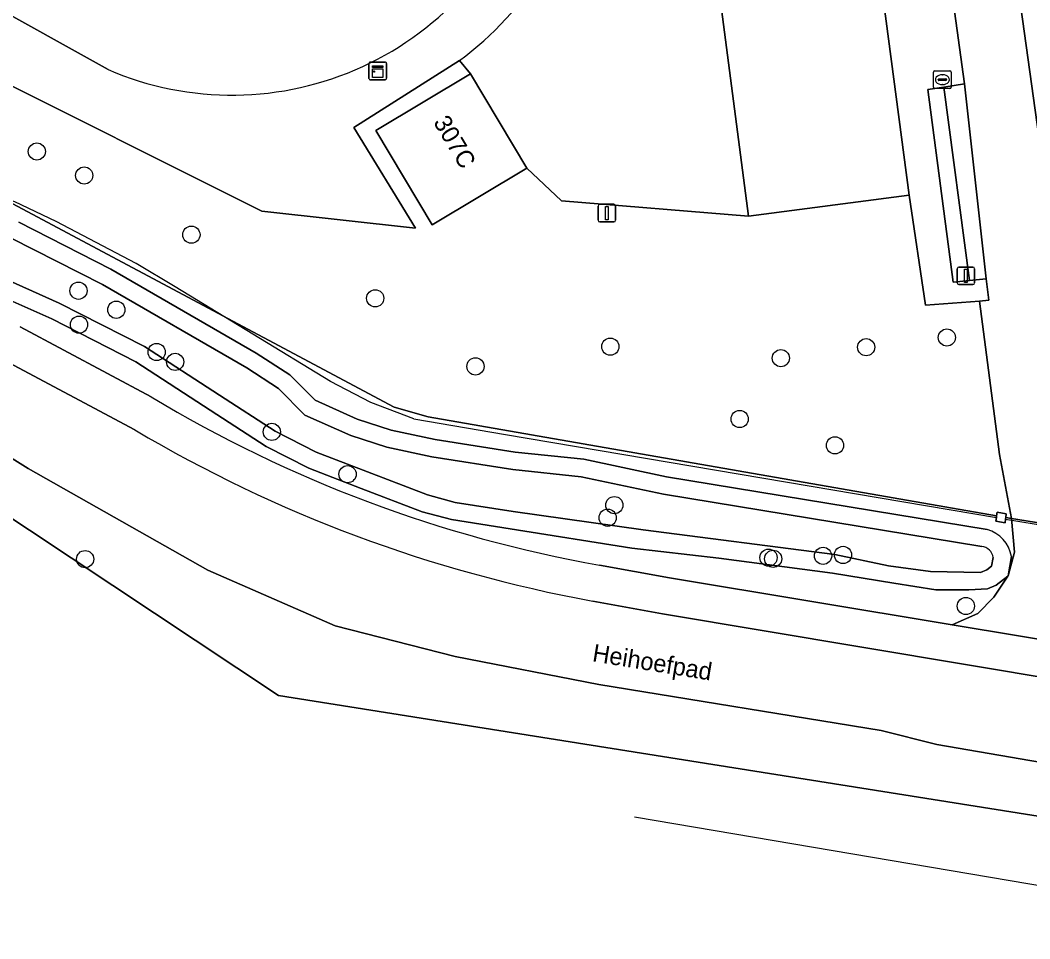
# Model space of a CAD drawing. Extents: x 162156 to 163172, y 378995 to 380779.
# Drawn here: x 162261.3 to 162318.7, y 379694.4 to 379746.6 of the extents above; entities that cross this region are included whole.
import ezdxf

# ---------------------------------------------------------------- set-up
doc = ezdxf.new("R2010")
doc.units = 0
for name, color, linetype in [('IMGEO_Boom', 7, 'Continuous'), ('IMGEO_Erf', 7, 'Continuous'), ('IMGEO_Fietspad_gesloten', 7, 'Continuous'), ('IMGEO_Grasland_overig', 7, 'Continuous'), ('IMGEO_Groenvoorziening', 7, 'Continuous'), ('IMGEO_Haag', 7, 'Continuous'), ('IMGEO_Hek', 7, 'Continuous'), ('IMGEO_Kast', 7, 'Continuous'), ('IMGEO_Kolk', 7, 'Continuous'), ('IMGEO_Lichtmast', 7, 'Continuous'), ('IMGEO_Loofbos', 7, 'Continuous'), ('IMGEO_Muur', 7, 'Continuous'), ('IMGEO_Oever', 7, 'Continuous'), ('IMGEO_Openbare_ruimte_label', 7, 'Continuous'), ('IMGEO_Pand', 7, 'Continuous'), ('IMGEO_Pand_nummerreeks', 7, 'Continuous'), ('IMGEO_Terreindeel_halfverhard', 7, 'Continuous'), ('IMGEO_Voetpad_gesloten', 7, 'Continuous'), ('IMGEO_Voetpad_open', 7, 'Continuous'), ('IMGEO_Waterloop', 7, 'Continuous')]:
    doc.layers.add(name, color=color, linetype=linetype)

msp = doc.modelspace()

# ---------------------------------------------------------------- linework, layer by layer
at = {"layer": 'IMGEO_Boom'}
for centre in [(162262.276, 379739.102), (162264.97, 379737.739), (162271.062, 379734.373), (162264.643, 379731.19), (162281.512, 379730.76), (162266.792, 379730.109), (162264.674, 379729.263), (162314.007, 379728.531), (162269.086, 379727.706), (162294.874, 379728.013), (162309.418, 379727.979), (162270.138, 379727.147), (162287.209, 379726.889), (162304.569, 379727.359), (162302.227, 379723.897), (162275.633, 379723.167), (162307.643, 379722.401), (162279.94, 379720.763), (162295.106, 379719.005), (162294.724, 379718.289), (162303.87, 379716.02), (162306.968, 379716.122), (162308.103, 379716.175), (162265.022, 379715.936), (162304.132, 379715.955), (162315.086, 379713.271)]:
    msp.add_circle(centre, 0.489, dxfattribs=at)
at = {"layer": 'IMGEO_Erf'}
msp.add_lwpolyline([(162337.174, 379688.677), (162335.238, 379695.41), (162334.723, 379697.203), (162334.223, 379698.94), (162276.018, 379708.183), (162252.426, 379723.827), (162232.664, 379729.795), (162201.08, 379730.479), (162201.347, 379726.944), (162202.006, 379718.214)], dxfattribs=at)
at = {"layer": 'IMGEO_Fietspad_gesloten'}
for points in [[(162268.773, 379725.159), (162261.33, 379729.13)], [(162260.378, 379727.269), (162267.847, 379723.281)], [(162413.482, 379695.459), (162407.265, 379696.651), (162406.548, 379696.772), (162403.9, 379697.219), (162359.692, 379704.679), (162325.622, 379710.328), (162314.3, 379712.205), (162298.239, 379714.868), (162294.268, 379715.593)], [(162293.883, 379713.556), (162297.835, 379712.825), (162406.505, 379694.666), (162426.261, 379691.023), (162431.745, 379689.857)]]:
    msp.add_lwpolyline(points, dxfattribs=at)
for centre, radius, start, end in [((162307.334, 379789.173), 74.731, 238.93594, 259.93079), ((162307.945, 379790.919), 78.631, 239.33886, 259.69768)]:
    msp.add_arc(centre, radius, start, end, dxfattribs=at)
at = {"layer": 'IMGEO_Grasland_overig'}
for points in [[(162214.541, 379733.002), (162226.745, 379733.002), (162231.259, 379732.528), (162235.614, 379731.527), (162241.895, 379730.106), (162247.114, 379728.274), (162254.858, 379725.049), (162258.235, 379723.285), (162261.79, 379721.082), (162272, 379715.314), (162279.233, 379712.147), (162286.048, 379710.401), (162294.223, 379708.812), (162310.274, 379706.198), (162313.432, 379705.394), (162326.545, 379703.142)], [(162267.847, 379723.281), (162260.378, 379727.269)], [(162297.835, 379712.825), (162293.883, 379713.556)], [(162431.745, 379689.857), (162426.261, 379691.023), (162406.505, 379694.666), (162297.835, 379712.825)]]:
    msp.add_lwpolyline(points, dxfattribs=at)
msp.add_arc((162307.945, 379790.919), 78.631, 239.33886, 259.69768, dxfattribs=at)
at = {"layer": 'IMGEO_Groenvoorziening'}
for points in [[(162308.264, 379818.798), (162308.342, 379818.234), (162319.23, 379739.952), (162323.504, 379740.549), (162323.904, 379737.397), (162326.096, 379737.669), (162325.701, 379740.847), (162354.391, 379744.94), (162352.739, 379754.146)], [(162245.107, 379755.565), (162200.542, 379780.028), (162207.281, 379761.484), (162206.713, 379759.494), (162208.417, 379755.264), (162211.499, 379752.19), (162220.789, 379751.034), (162244.456, 379751.721), (162246.14, 379754.783), (162260.156, 379747.07), (162258.472, 379744.009), (162275.07, 379735.712), (162283.803, 379734.743), (162280.296, 379740.465), (162286.296, 379744.277)], [(162266.322, 379743.758), (162245.107, 379755.565)], [(162260.586, 379736.299), (162282.584, 379724.579), (162284.522, 379724.017), (162316.836, 379718.388), (162316.869, 379718.597), (162317.383, 379718.517), (162317.353, 379718.304), (162317.673, 379718.252), (162317.006, 379721.885), (162315.86, 379730.604), (162312.79, 379730.368), (162311.854, 379736.618), (162302.724, 379735.425), (162292.108, 379736.3), (162290.138, 379738.153), (162284.754, 379734.934), (162281.544, 379740.303), (162286.928, 379743.522), (162286.296, 379744.277), (162280.296, 379740.465), (162283.803, 379734.743), (162275.07, 379735.712), (162258.472, 379744.009)], [(162296.1, 379716.558), (162289.191, 379717.652), (162285.844, 379718.182), (162284.173, 379718.63), (162280.713, 379719.958), (162277.745, 379721.098), (162275.315, 379722.336), (162272.124, 379724.409), (162267.9, 379727.151), (162263.121, 379729.586), (162259.537, 379731.182), (162256.304, 379732.621), (162252.721, 379733.786), (162245.305, 379736.068)], [(162317.68, 379716.09), (162317.487, 379714.992), (162317.854, 379716.332), (162317.673, 379718.252), (162317.353, 379718.304), (162317.34, 379718.213), (162317.31, 379718), (162316.79, 379718.091), (162316.822, 379718.298), (162316.836, 379718.388), (162284.522, 379724.017), (162282.584, 379724.579), (162260.586, 379736.299)], [(162261.252, 379735.081), (162266.481, 379732.417), (162274.735, 379727.651), (162276.648, 379726.409), (162278.096, 379724.962), (162280.479, 379723.9), (162282.421, 379723.269), (162284.911, 379722.74), (162289.465, 379722.019), (162293.375, 379721.608), (162298.069, 379720.61), (162316.295, 379717.625)], [(162261.33, 379729.13), (162268.773, 379725.159)], [(162294.268, 379715.593), (162298.239, 379714.868), (162314.3, 379712.205), (162315.759, 379712.85), (162316.676, 379713.773), (162317.48, 379714.967), (162316.802, 379714.457), (162316.306, 379714.252), (162315.256, 379714.197), (162313.385, 379714.197), (162310.997, 379714.575), (162307.496, 379715.13), (162301.046, 379715.997), (162296.1, 379716.558)]]:
    msp.add_lwpolyline(points, dxfattribs=at)
for points in [[(162314.999, 379742.94), (162313.835, 379742.763), (162315.296, 379731.777), (162316.244, 379731.87)], [(162313.835, 379742.763), (162312.925, 379742.625), (162314.36, 379731.685), (162315.296, 379731.777)]]:
    msp.add_lwpolyline(points, close=True, dxfattribs=at)
for centre, radius, start, end in [((162276.161, 379758.307), 17.307, 305.84362, 352.61508), ((162273.362, 379760.093), 17.788, 246.68434, 342.76247), ((162307.334, 379789.173), 74.731, 238.93594, 259.93079), ((162315.75, 379715.741), 1.961, 10.24618, 73.87244)]:
    msp.add_arc(centre, radius, start, end, dxfattribs=at)
at = {"layer": 'IMGEO_Haag'}
msp.add_lwpolyline([(162313.835, 379742.763), (162312.925, 379742.625), (162314.36, 379731.685), (162315.296, 379731.777)], close=True, dxfattribs=at)
at = {"layer": 'IMGEO_Hek'}
for points in [[(162266.322, 379743.758), (162245.107, 379755.565), (162200.542, 379780.028)], [(162283.7, 379723.919), (162281.26, 379724.831), (162278.962, 379726.037), (162270.138, 379731.405), (162267.925, 379732.742), (162263.368, 379735.129), (162261.032, 379736.236), (162253.819, 379738.605), (162239.147, 379743.541)], [(162283.7, 379723.919), (162288.918, 379723.028)], [(162288.918, 379723.028), (162316.822, 379718.298)], [(162317.34, 379718.213), (162322.451, 379717.379)], [(162332.134, 379695.194), (162296.257, 379701.272)]]:
    msp.add_lwpolyline(points, dxfattribs=at)
msp.add_arc((162273.362, 379760.093), 17.788, 246.68434, 342.76247, dxfattribs=at)
at = {"layer": 'IMGEO_Kast'}
for p, q in [((162281.155, 379743.255), (162281.155, 379744.096)), ((162281.155, 379744.096), (162281.155, 379743.255)), ((162281.23, 379744.18), (162282.071, 379744.18)), ((162282.071, 379744.18), (162281.23, 379744.18)), ((162282.155, 379744.105), (162282.155, 379743.264)), ((162282.155, 379743.264), (162282.155, 379744.105)), ((162282.08, 379743.18), (162281.239, 379743.18)), ((162281.239, 379743.18), (162282.08, 379743.18))]:
    msp.add_line(p, q, dxfattribs=at)
for points in [[(162281.35, 379743.97), (162281.95, 379743.97), (162281.95, 379743.885), (162281.35, 379743.885), (162281.35, 379743.97)], [(162281.35, 379743.795), (162281.95, 379743.795), (162281.95, 379743.306), (162281.35, 379743.306), (162281.35, 379743.795)]]:
    msp.add_lwpolyline(points, dxfattribs=at)
msp.add_circle((162281.434, 379743.644), 0.0377, dxfattribs=at)
for centre, start, end in [((162281.233, 379744.102), 92.4484, 184.28452), ((162281.233, 379744.102), 92.4484, 184.28452), ((162282.077, 379744.102), 2.4484, 94.28452), ((162282.077, 379744.102), 2.4484, 94.28452), ((162281.233, 379743.258), 182.4484, 274.28452), ((162281.233, 379743.258), 182.4484, 274.28452), ((162282.077, 379743.258), 272.4484, 4.28452), ((162282.077, 379743.258), 272.4484, 4.28452)]:
    msp.add_arc(centre, 0.0779, start, end, dxfattribs=at)
at = {"layer": 'IMGEO_Kolk'}
for p, q in [((162313.25, 379742.758), (162313.25, 379743.61)), ((162313.325, 379743.684), (162314.177, 379743.684)), ((162313.738, 379743.464), (162313.763, 379743.464)), ((162314.251, 379743.61), (162314.251, 379742.758)), ((162313.509, 379743.178), (162313.509, 379743.19)), ((162313.947, 379743.141), (162313.549, 379743.141)), ((162313.552, 379743.227), (162313.95, 379743.227)), ((162313.761, 379742.904), (162313.736, 379742.904)), ((162313.993, 379743.19), (162313.993, 379743.178)), ((162314.177, 379742.684), (162313.325, 379742.684))]:
    msp.add_line(p, q, dxfattribs=at)
for points in [[(162313.25, 379742.758), (162313.25, 379743.61)], [(162313.325, 379743.684), (162314.177, 379743.684)], [(162314.251, 379743.61), (162314.251, 379742.758)], [(162314.177, 379742.684), (162313.325, 379742.684)]]:
    msp.add_lwpolyline(points, dxfattribs=at)
for centre, radius, start, end in [((162313.327, 379743.608), 0.0765, 91.55205, 178.44795), ((162313.327, 379743.608), 0.0765, 91.55205, 178.44795), ((162314.175, 379743.608), 0.0765, 1.55205, 88.44795), ((162314.175, 379743.608), 0.0765, 1.55205, 88.44795), ((162313.549, 379743.187), 0.0403, 85.87752, 175.75265), ((162313.546, 379743.177), 0.0366, 178.93798, 274.71019), ((162313.95, 379743.184), 0.043, 264.86636, 352.45326), ((162313.954, 379743.189), 0.0386, 1.73085, 96.63898), ((162313.327, 379742.76), 0.0765, 181.55205, 268.44795), ((162313.327, 379742.76), 0.0765, 181.55205, 268.44795), ((162314.175, 379742.76), 0.0765, 271.55205, 358.44795), ((162314.175, 379742.76), 0.0765, 271.55205, 358.44795)]:
    msp.add_arc(centre, radius, start, end, dxfattribs=at)
for centre, major_axis, ratio, start_param, end_param in [((162313.737, 379743.184), (-0.387, 0.002), 0.722429, 4.712389, 7.853982), ((162313.762, 379743.184), (-0.39, 0.002), 0.717154, 1.570796, 4.712389)]:
    msp.add_ellipse(centre, major_axis=major_axis, ratio=ratio, start_param=start_param, end_param=end_param, dxfattribs=at)
at = {"layer": 'IMGEO_Lichtmast'}
for p, q in [((162294.181, 379735.202), (162294.181, 379736.002)), ((162294.181, 379736.002), (162294.181, 379735.202)), ((162294.281, 379736.102), (162295.071, 379736.102)), ((162295.071, 379736.102), (162294.281, 379736.102)), ((162295.171, 379736.002), (162295.171, 379735.202)), ((162295.171, 379735.202), (162295.171, 379736.002)), ((162295.071, 379735.102), (162294.281, 379735.102)), ((162294.281, 379735.102), (162295.071, 379735.102)), ((162314.691, 379732.538), (162315.481, 379732.538)), ((162315.481, 379732.538), (162314.691, 379732.538)), ((162314.591, 379731.638), (162314.591, 379732.438)), ((162314.591, 379732.438), (162314.591, 379731.638)), ((162315.581, 379732.438), (162315.581, 379731.638)), ((162315.581, 379731.638), (162315.581, 379732.438)), ((162315.481, 379731.538), (162314.691, 379731.538)), ((162314.691, 379731.538), (162315.481, 379731.538))]:
    msp.add_line(p, q, dxfattribs=at)
for points in [[(162294.601, 379735.977), (162294.751, 379735.977), (162294.751, 379735.227), (162294.601, 379735.227), (162294.601, 379735.977)], [(162315.011, 379732.413), (162315.161, 379732.413), (162315.161, 379731.663), (162315.011, 379731.663), (162315.011, 379732.413)]]:
    msp.add_lwpolyline(points, dxfattribs=at)
for centre, start, end in [((162294.281, 379736.002), 90, 180), ((162294.281, 379736.002), 90, 180), ((162295.071, 379736.002), 0, 90), ((162295.071, 379736.002), 360, 90), ((162294.281, 379735.202), 180, 270), ((162294.281, 379735.202), 180, 270), ((162295.071, 379735.202), 270, 0), ((162295.071, 379735.202), 270, 0), ((162314.691, 379732.438), 90, 180), ((162314.691, 379732.438), 90, 180), ((162315.481, 379732.438), 0, 90), ((162315.481, 379732.438), 360, 90), ((162314.691, 379731.638), 180, 270), ((162314.691, 379731.638), 180, 270), ((162315.481, 379731.638), 270, 0), ((162315.481, 379731.638), 270, 0)]:
    msp.add_arc(centre, 0.1, start, end, dxfattribs=at)
at = {"layer": 'IMGEO_Loofbos'}
for points in [[(162235.614, 379731.527), (162231.259, 379732.528), (162226.745, 379733.002), (162214.541, 379733.002), (162205.491, 379732.528), (162200.706, 379732.277), (162201.08, 379730.479), (162232.664, 379729.795), (162252.426, 379723.827), (162276.018, 379708.183), (162334.223, 379698.94), (162336.989, 379698.762)], [(162329.924, 379702.799), (162326.545, 379703.142), (162313.432, 379705.394), (162310.274, 379706.198), (162294.223, 379708.812), (162286.048, 379710.401), (162279.233, 379712.147), (162272, 379715.314), (162261.79, 379721.082), (162258.235, 379723.285), (162254.858, 379725.049), (162247.114, 379728.274), (162241.895, 379730.106), (162235.614, 379731.527)]]:
    msp.add_lwpolyline(points, dxfattribs=at)
at = {"layer": 'IMGEO_Muur'}
msp.add_lwpolyline([(162317.353, 379718.304), (162317.383, 379718.517), (162316.869, 379718.597), (162316.836, 379718.388), (162316.822, 379718.298), (162316.79, 379718.091), (162317.31, 379718), (162317.34, 379718.213)], close=True, dxfattribs=at)
at = {"layer": 'IMGEO_Oever'}
for points in [[(162316.295, 379717.625), (162298.069, 379720.61), (162293.375, 379721.608), (162289.465, 379722.019), (162284.911, 379722.74), (162282.421, 379723.269), (162280.479, 379723.9), (162278.096, 379724.962), (162276.648, 379726.409), (162274.735, 379727.651), (162266.481, 379732.417), (162261.252, 379735.081)], [(162260.821, 379734.178), (162266.004, 379731.538), (162274.212, 379726.799), (162276.015, 379725.628), (162277.519, 379724.123), (162280.12, 379722.966), (162282.162, 379722.302), (162284.729, 379721.757), (162289.335, 379721.027), (162293.218, 379720.619), (162297.898, 379719.624), (162315.994, 379716.663)], [(162316.645, 379716.03), (162316.541, 379715.543), (162316.278, 379715.322), (162315.924, 379715.176), (162313.082, 379715.232), (162310.683, 379715.554), (162307.645, 379716.196), (162296.749, 379717.606), (162289.347, 379718.64), (162286.053, 379719.162), (162284.483, 379719.583), (162281.071, 379720.892), (162278.153, 379722.012), (162275.816, 379723.203), (162272.668, 379725.247), (162268.401, 379728.018), (162263.552, 379730.489), (162259.944, 379732.095)], [(162259.537, 379731.182), (162263.121, 379729.586), (162267.9, 379727.151), (162272.124, 379724.409), (162275.315, 379722.336), (162277.745, 379721.098), (162280.713, 379719.958), (162284.173, 379718.63), (162285.844, 379718.182), (162289.191, 379717.652), (162296.1, 379716.558), (162301.046, 379715.997), (162307.496, 379715.13), (162310.997, 379714.575), (162313.385, 379714.197), (162315.256, 379714.197), (162316.306, 379714.252), (162316.802, 379714.457), (162317.48, 379714.967), (162317.487, 379714.992), (162317.68, 379716.09)]]:
    msp.add_lwpolyline(points, dxfattribs=at)
for centre, radius, start, end in [((162315.75, 379715.741), 1.961, 10.24618, 73.87244), ((162315.873, 379715.887), 0.785, 10.47592, 81.1304)]:
    msp.add_arc(centre, radius, start, end, dxfattribs=at)
at = {"layer": 'IMGEO_Pand'}
for points in [[(162310.261, 379748.822), (162301.13, 379747.629), (162302.724, 379735.425), (162311.854, 379736.618)], [(162286.928, 379743.522), (162281.544, 379740.303), (162284.754, 379734.934), (162290.138, 379738.153)]]:
    msp.add_lwpolyline(points, close=True, dxfattribs=at)
at = {"layer": 'IMGEO_Terreindeel_halfverhard'}
msp.add_lwpolyline([(162201.994, 379852.701), (162196.567, 379837.412), (162189.38, 379817.166), (162184.816, 379804.307), (162181.657, 379795.408), (162181.289, 379794.37), (162181.144, 379793.961), (162182.316, 379790.033), (162183.312, 379789.486), (162184.278, 379788.956), (162200.542, 379780.028), (162245.107, 379755.565), (162266.322, 379743.758)], dxfattribs=at)
msp.add_arc((162273.362, 379760.093), 17.788, 246.68434, 342.76247, dxfattribs=at)
at = {"layer": 'IMGEO_Voetpad_gesloten'}
msp.add_lwpolyline([(162308.342, 379818.234), (162304.71, 379817.94), (162304.57, 379817.929), (162304.658, 379817.281), (162305.336, 379812.297), (162312.638, 379758.611), (162313.486, 379751.686), (162313.807, 379751.65), (162314.999, 379742.94), (162316.244, 379731.87), (162316.4, 379730.646), (162315.86, 379730.604), (162317.006, 379721.885), (162317.673, 379718.252), (162321.707, 379717.594), (162322.285, 379717.503), (162321.734, 379721.551), (162320.652, 379729.505), (162320.127, 379733.361), (162319.773, 379735.962), (162319.659, 379736.804), (162319.23, 379739.952)], close=True, dxfattribs=at)
at = {"layer": 'IMGEO_Voetpad_open'}
for points in [[(162310.261, 379748.822), (162311.854, 379736.618), (162312.79, 379730.368), (162315.86, 379730.604), (162316.4, 379730.646), (162316.244, 379731.87), (162315.296, 379731.777), (162314.36, 379731.685), (162312.925, 379742.625), (162313.835, 379742.763), (162314.999, 379742.94), (162313.807, 379751.65), (162313.486, 379751.686), (162312.638, 379758.611), (162298.518, 379756.791), (162298.658, 379755.435), (162293.325, 379756.082)], [(162286.296, 379744.277), (162286.928, 379743.522), (162290.138, 379738.153), (162292.108, 379736.3), (162302.724, 379735.425), (162301.13, 379747.629), (162310.261, 379748.822)], [(162322.299, 379714.074), (162322.285, 379717.503), (162321.707, 379717.594), (162317.673, 379718.252), (162317.854, 379716.332), (162317.487, 379714.992), (162317.48, 379714.967), (162316.676, 379713.773), (162315.759, 379712.85), (162314.3, 379712.205), (162325.622, 379710.328), (162322.985, 379712.621)]]:
    msp.add_lwpolyline(points, dxfattribs=at)
msp.add_arc((162276.161, 379758.307), 17.307, 305.84362, 352.61508, dxfattribs=at)
at = {"layer": 'IMGEO_Waterloop'}
for points in [[(162315.994, 379716.663), (162297.898, 379719.624), (162293.218, 379720.619), (162289.335, 379721.027), (162284.729, 379721.757), (162282.162, 379722.302), (162280.12, 379722.966), (162277.519, 379724.123), (162276.015, 379725.628), (162274.212, 379726.799), (162266.004, 379731.538), (162260.821, 379734.178)], [(162259.944, 379732.095), (162263.552, 379730.489), (162268.401, 379728.018), (162272.668, 379725.247), (162275.816, 379723.203), (162278.153, 379722.012), (162281.071, 379720.892), (162284.483, 379719.583), (162286.053, 379719.162), (162289.347, 379718.64), (162296.749, 379717.606), (162307.645, 379716.196), (162310.683, 379715.554), (162313.082, 379715.232), (162315.924, 379715.176), (162316.278, 379715.322), (162316.541, 379715.543), (162316.645, 379716.03)]]:
    msp.add_lwpolyline(points, dxfattribs=at)
msp.add_arc((162315.873, 379715.887), 0.785, 10.47592, 81.1304, dxfattribs=at)

# ---------------------------------------------------------------- texts
at = {"layer": 'IMGEO_Openbare_ruimte_label'}
msp.add_text('Heihoefpad', height=1, rotation=350.73548, dxfattribs=at).set_placement((162293.812, 379710.136))
at = {"layer": 'IMGEO_Pand_nummerreeks'}
msp.add_text('307C', height=1, rotation=300.87649, dxfattribs=at).set_placement((162284.787, 379740.77))

doc.saveas('drawing.dxf')
